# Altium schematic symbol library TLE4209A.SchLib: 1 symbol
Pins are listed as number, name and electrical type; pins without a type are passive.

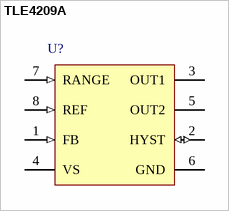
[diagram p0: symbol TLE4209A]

## TLE4209A
designator U?
DC Motor Driver for Servo Driver Applications, -40 to 150 degC, PG-DIP-8-4, Tube, Green; Manufacturer: Infineon; PartNumber: TLE4209A; Green: TRUE; Inhibit: FALSE; IPeak: 2 x 1 A; Iq: 2 x 0.8 A; Iq (typ): 10 uA; Protect: short circuit e.a.
footprint INF-PG-DIP-8-4 (DIP, 8-Leads, Body 9.52x6.35mm, Pitch 2.54mm)
pins: 1 FB (in) "Feedback Input", 2 HYST (io) "Hysteresis I/O", 3 OUT1 (power) "Power Output 1", 4 VS (power) "Power Supply Voltage", 5 OUT2 (power) "Power Output 2", 6 GND (power) "Ground", 7 RANGE (in) "Range Input", 8 REF (in) "Reference Input"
